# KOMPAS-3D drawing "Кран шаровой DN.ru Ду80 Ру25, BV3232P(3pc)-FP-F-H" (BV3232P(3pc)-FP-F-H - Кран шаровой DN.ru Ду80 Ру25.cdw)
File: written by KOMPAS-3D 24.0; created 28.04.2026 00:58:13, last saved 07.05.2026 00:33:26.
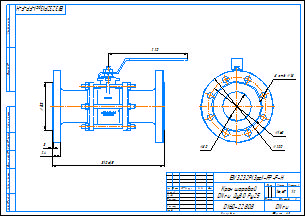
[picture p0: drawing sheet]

Document properties: Автор: Максим; Форматы листов документа: A3; Полное имя файла: BVxxP(3pc)-FP-F-H - Кран шаровой DN.ru Ду80 Ру25.cdw; Масса: 16.665; Наименование: Кран шаровой DN.ru Ду80 Ру25; Количество листов документа: 1; Примечание: D160-22808

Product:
- Body: Тело 1  | qty 1
    Масса: 14.35719
- Part/product: Кран шаровой DN.ru Ду80 Ру25  | designation BV3232P(3pc)-FP-F-H
    Масса: 16.665
    Раздел спецификации: Прочие изделия
    Форматы листов документа: A3
    Примечание: D160-22808

Views: Вид 1, Вид:2, Проекционный вид 2, Вид:1
Referenced files in D:\Rabota ebanaya\Апрель\BVxxP(3pc)-FP-F-H Кран шаровой Ду15-100\Исходники\DN80\: BVxxP(3pc)-FP-F-H - Кран шаровой DN.ru Ду80 Ру25.m3d, BVxxP(3pc)-FP-F-H - Кран шаровой DN.ru Ду80 Ру25.cdw
Referenced files in D:\Rabota ebanaya\Апрель\BV3232P(3pc)-FP-F-H Кран шаровой Ду15-100\Исходники\DN80\: BV3232P(3pc)-FP-F-H - Кран шаровой DN.ru Ду80 Ру25.m3d
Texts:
  Линейный размер
  BV3232P(3pc)-FP-F-H
  Диаметральный размер
  Кран шаровой
  DN.ru Ду80 Ру25
  Кран шаровой DN.ru Ду80 Ру25
  BV3232P(3pc)-FP-F-H Кран шаровой DN.ru Ду80 Ру25
Dimensions and other numbers on the sheet: 0; 3; 2; 4; 310±1,5; 220; 24; 133; 8 отв.; 18; 200; 80; 160; 1:2; 1; 16,67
